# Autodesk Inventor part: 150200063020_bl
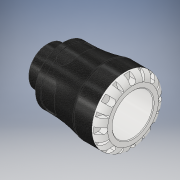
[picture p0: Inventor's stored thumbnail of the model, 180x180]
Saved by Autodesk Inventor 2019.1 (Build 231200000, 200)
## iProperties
Created: 2016-12
Part Number: 150200063020_bl
Material: PVC-Piping
Description: PLASSON G-PLASS Male Adaptor 63X 2''
Document SubType Name: Modeling
Designer: KIM
Mass: 61.7504 g
Surface Area: 140.097 cm^2
Volume: 44.1074 cm^3
Density: 1.4 g/cm^3
Appearance: Black Cast
Author: KIM
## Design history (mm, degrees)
derived "150200.ipt"
feature "Solid1::150200.ipt" dims "ScaleForDerivedMember" = 10
tag "TaggingFeature1"
body "Solid1"
other parameters: "d0" = 133 [user parameter], "d1" = 40.74 [user parameter], "d2" = 63 [user parameter], "d3" = 78.75 [user parameter], "d4" = 103 [user parameter], "d6" = 97 [user parameter], "d8" = 87.55 [user parameter], "d13" = 9.7 [user parameter], "d14" = 9.7 [user parameter], "d15" = 0 [user parameter], "d17" = 360 deg [user parameter], "d19" = 8 deg [user parameter], "d20" = 1.26 [user parameter], "d21" = 1.26 [user parameter], "d22" = 8 deg [user parameter], "d24" = 0 [user parameter], "d26" = 360 deg [user parameter], "d32" = 0.925 [user parameter], "d33" = 10.3 [user parameter], "d34" = 59.614 [user parameter], "d35" = 7.875 [user parameter], "d38" = 25 [user parameter], "d39" = 1.78842 [user parameter], "d42" = 22.05 [user parameter], "d43" = 14.49 [user parameter], "d45" = 19.012 [user parameter], "d46" = 0 [user parameter], "d59" = 360 deg [user parameter], "d61" = 18.7425 [user parameter], "d62" = 1.26 [user parameter], "d64" = 0 [user parameter], "d65" = 1.03 [user parameter], "d_" = 63 [user parameter], "E_" = 103 [user parameter], "H_" = 133 [user parameter], "l_" = 97 [user parameter], "R_" = 59.614 [user parameter], "l_2" = 25 [user parameter], "d9" = 12.125 [user parameter], "d11" = 103 [user parameter], "d12" = 78.75 [user parameter]
